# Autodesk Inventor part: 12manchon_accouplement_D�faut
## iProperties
Created: 2011-01
Part Number: 12manchon_accouplement_D�faut
Document SubType Name: Modeling
Designer: eric
Density: 1 g/cm^3
Mass: 3.50332 g
Surface Area: 22.6127 cm^2
Volume: 3.50332 cm^3
Author: eric
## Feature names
1. Base1
